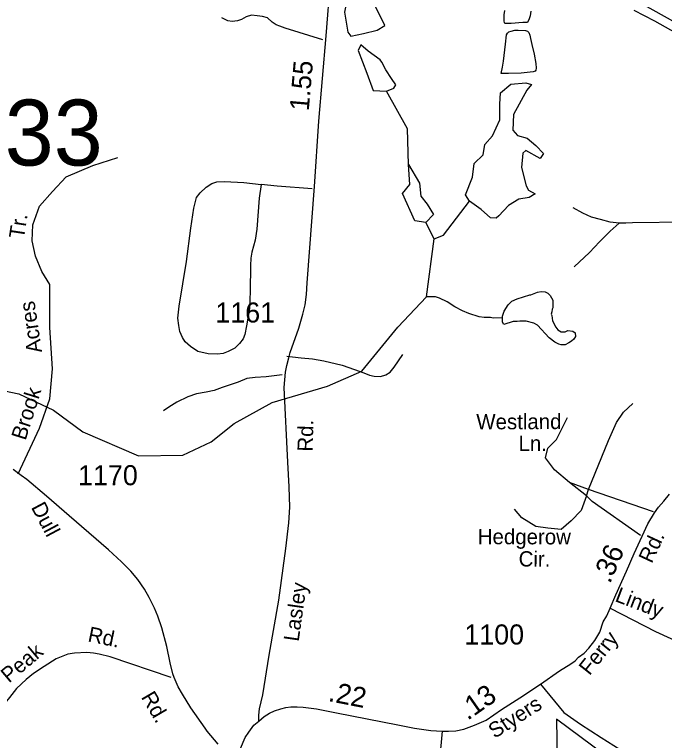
# Model space of a CAD drawing. Extents: x 1547597 to 1699558, y 810033 to 920809.
# Drawn here: x 1580417 to 1584459, y 847300 to 851817 of the extents above; entities that cross this region are included whole.
import ezdxf

# ---------------------------------------------------------------- set-up
doc = ezdxf.new("R2010")
doc.units = 0
for name, color, linetype in [('Exist Boundary Political City Limit New', 7, 'Continuous'), ('Exist Hydrographic Misc Water Feature', 7, 'Continuous'), ('Exist Road Non-System Type 51', 7, 'Continuous'), ('Exist Road Non-System Type 51 Label', 7, 'Continuous'), ('Exist Road Primary US Divided Attributed', 7, 'Continuous'), ('Exist Road Secondary Mileage Hundredths English Label', 7, 'Continuous'), ('Exist Road Secondary Structure Pipe Number Label', 7, 'Continuous'), ('Exist Road Secondary Type 51 Attributed', 7, 'Continuous'), ('Exist Road Secondary Type 51 Label', 7, 'Continuous'), ('Exist Road Secondary Type 51 Number Label', 7, 'Continuous'), ('Map Preparation Boundary City Limit Buffer Line', 7, 'Continuous')]:
    doc.layers.add(name, color=color, linetype=linetype)

msp = doc.modelspace()

# ---------------------------------------------------------------- linework, layer by layer
at = {"layer": 'Exist Boundary Political City Limit New'}
msp.add_lwpolyline([(1584449.8, 846940.3), (1583788.1, 847433.2), (1583808.3, 846129.1)], dxfattribs=at)
at = {"layer": 'Exist Hydrographic Misc Water Feature'}
for points in [[(1582621.5, 851982.6), (1582525, 851980), (1582492.9, 851942.4), (1582468.8, 851832.4), (1582490.2, 851706.4), (1582509, 851682.2), (1582586.7, 851698.3), (1582672.4, 851719.8), (1582720.7, 851749.3), (1582664.4, 851861.9), (1582621.5, 851982.6)], [(1583627.8, 851837.8), (1583623.1, 851809.1), (1583618.6, 851790), (1583606.8, 851768), (1583579.3, 851766.2), (1583506.7, 851761.5), (1583467.7, 851761.6), (1583464.8, 851765.8), (1583461.5, 851777.9), (1583462.7, 851813.8), (1583466.7, 851841.9)], [(1583635.1, 851629.9), (1583648.8, 851570.5), (1583659.3, 851511.6), (1583661.9, 851482.2), (1583659.9, 851470.7), (1583655.8, 851464.5), (1583643.3, 851460.3), (1583568.9, 851452.8), (1583489.2, 851448.9), (1583443.4, 851449.2), (1583452.9, 851489.1), (1583458.5, 851525.9), (1583470.6, 851632.9), (1583477.8, 851690.6), (1583482.4, 851700.8), (1583491.9, 851709.5), (1583506.2, 851714.1), (1583529, 851719), (1583549.4, 851720), (1583594.8, 851717.9), (1583607.7, 851713.2), (1583615, 851704.6), (1583621.9, 851688.9), (1583626.4, 851667.9), (1583630.1, 851649.2), (1583635.1, 851629.9)], [(1582691.2, 851534.7), (1582616.1, 851588.4), (1582570.6, 851628.6), (1582554.5, 851593.7), (1582608.1, 851451.6), (1582648.3, 851344.3), (1582731.4, 851338.9)], [(1582731.4, 851338.9), (1582776.9, 851357.7), (1582787.7, 851379.2), (1582760.9, 851419.4), (1582726, 851473), (1582701.9, 851521.3), (1582691.2, 851534.7)], [(1583246, 850656.3), (1583221.9, 850693.8), (1583264.8, 850803.8), (1583275.5, 850889.6), (1583331.8, 850943.3), (1583342.5, 851007.7), (1583390.7, 851061.3), (1583436.3, 851160.5), (1583436.3, 851259.8), (1583439, 851329.5), (1583503.3, 851383.1), (1583597.1, 851391.2), (1583631.9, 851380.5), (1583602.4, 851345.6), (1583519.4, 851195.4), (1583516.7, 851096.2), (1583546.2, 851064), (1583605.1, 851047.9), (1583658.7, 851002.3), (1583706.9, 850951.3), (1583685.5, 850921.8), (1583597.1, 850970.1), (1583578.3, 850954), (1583570.3, 850865.5), (1583599.8, 850750.2), (1583613.2, 850723.4), (1583656, 850701.9), (1583618.5, 850677.8), (1583554.2, 850667), (1583489.9, 850629.5), (1583428.3, 850565.1), (1583412.2, 850549), (1583377.3, 850551.7), (1583318.4, 850602.7), (1583246, 850656.3)], [(1583026.1, 850420.4), (1582975.7, 850522.8), (1582906.7, 850533.4), (1582829.7, 850703.4), (1582874.9, 850759.2), (1582866.9, 850884), (1582860.5, 851105.4), (1582731.4, 851338.9)], [(1582866.9, 850884), (1582935.9, 850767.1), (1582943.9, 850687.4), (1582983.7, 850637), (1583023.5, 850573.2), (1582975.7, 850522.8)], [(1583026.1, 850420.4), (1583084.5, 850444.3), (1583246, 850656.3)], [(1579738.9, 849483.7), (1580094.5, 849530), (1580443.5, 849457.2), (1580659.6, 849354.4), (1580840.5, 849219.4), (1581188.5, 849071.2), (1581463.5, 849075.5), (1581640.5, 849157.3), (1581783.6, 849272.5), (1582018.6, 849402.3), (1582362.5, 849503.7), (1582577.6, 849597), (1582800.5, 849870.6), (1582979.3, 850060.4), (1583026.1, 850420.4)], [(1583451.4, 849929.6), (1583451.5, 849939), (1583461.9, 849970.9), (1583486.3, 850010.6), (1583510.6, 850032.3), (1583542.8, 850047.8), (1583621, 850072.9), (1583629, 850072.7), (1583669.2, 850088.2), (1583693.3, 850093.9), (1583717.3, 850091.6), (1583733.2, 850083.4), (1583749, 850069.2), (1583764.7, 850039), (1583764, 849991.1), (1583759.9, 849983.1), (1583759.7, 849967.1), (1583755.6, 849953.2), (1583759.5, 849943.2), (1583763.1, 849911.1), (1583784.7, 849870.9), (1583796.4, 849854.7), (1583816.3, 849842.5), (1583842.3, 849842.2), (1583858.4, 849850), (1583890.4, 849847.5), (1583904.2, 849835.3), (1583905.9, 849813.4), (1583895.7, 849797.5), (1583881.5, 849783.7), (1583865.4, 849773.9), (1583841.3, 849762.2), (1583817.4, 849762.5), (1583801.4, 849766.7), (1583777.6, 849779), (1583741.9, 849805.4), (1583668.8, 849884.3), (1583647, 849896.6), (1583599.1, 849909.2), (1583559.1, 849909.7), (1583543.1, 849905.9), (1583519.1, 849906.2), (1583460.1, 849887.3), (1583451, 849903), (1583451.2, 849915), (1583451.4, 849929.6)], [(1583451.4, 849929.6), (1583394, 849927.3), (1583378, 849931.5), (1583338.1, 849932), (1583306.2, 849936.4), (1583242.4, 849957.2), (1583202.6, 849973.7), (1583154.9, 849998.3), (1583107.3, 850028.9), (1583059.6, 850051.5), (1583035.6, 850059.8), (1582979.3, 850060.4)]]:
    msp.add_lwpolyline(points, dxfattribs=at)
at = {"layer": 'Exist Road Non-System Type 51'}
for points in [[(1582334.7, 851660), (1582100.7, 851732.8), (1582066.9, 851743.3), (1582043.1, 851753.6), (1582019.4, 851769.8), (1581989.7, 851796.5), (1581959.6, 851804.9), (1581925.7, 851809.4), (1581889.8, 851811.9), (1581857.7, 851802.3), (1581829.4, 851786.7), (1581803.2, 851777), (1581771.3, 851773.5), (1581743.2, 851777.8), (1581705.5, 851796.4)], [(1580440, 848959.9), (1580571.3, 849243.8), (1580636.8, 849425.3), (1580651.9, 849611.8), (1580636.8, 849868.9), (1580636.8, 850136.2), (1580586.4, 850216.8), (1580546.1, 850312.6), (1580525.9, 850408.4), (1580531, 850509.2), (1580571.3, 850625.2), (1580651.9, 850715.9), (1580737.5, 850806.7), (1580903.8, 850877.3), (1581059.9, 850927.7)], [(1582267.1, 850731.8), (1582050.6, 850748.4), (1581950.7, 850758.7)], [(1584178.3, 850518), (1584122.2, 850525), (1584060.5, 850541.8), (1584004.5, 850556.6), (1583951, 850581.5), (1583891.4, 850614.3)], [(1584178.3, 850518), (1584121.4, 850469), (1584054.4, 850401.9), (1583993.5, 850336.7), (1583898, 850246)], [(1584927.7, 850529.5), (1584260.2, 850521), (1584218.3, 850519.4), (1584178.3, 850518)], [(1582110.2, 849691.5), (1582199.2, 849680.4), (1582269.1, 849673.4), (1582340.9, 849662.3), (1582454.6, 849634.6), (1582532.3, 849607.4), (1582589.9, 849586.7), (1582623.8, 849572.2), (1582653.7, 849565.8), (1582693.7, 849565.2), (1582725.7, 849574.7), (1582754.1, 849592.3), (1582778.5, 849621.9), (1582831.8, 849701.2)], [(1582081.1, 849575), (1581981.2, 849561.4), (1581913.1, 849558.3), (1581861.2, 849551.2), (1581808.7, 849529.8), (1581708.2, 849495.5), (1581658, 849478.1), (1581607.7, 849466.9), (1581549.5, 849455.7), (1581495.3, 849438.3), (1581426.8, 849405.3), (1581376.3, 849374.1), (1581344, 849350.6)], [(1583986.1, 848861.4), (1584111.3, 849166), (1584160.3, 849279), (1584204.5, 849342.9), (1584263.4, 849396.9)], [(1583868.3, 848905.6), (1583775, 848984.2), (1583718.6, 849057.9), (1583733.3, 849119.3), (1583787.3, 849173.4), (1583856, 849308.5)], [(1583973.8, 848822.1), (1583868.3, 848905.6)], [(1583986.1, 848861.4), (1583868.3, 848905.6)], [(1583973.8, 848822.1), (1583941.9, 848731.3), (1583878.1, 848667.4), (1583816.7, 848613.3), (1583733.3, 848620.7), (1583659.6, 848630.5), (1583571.3, 848684.6), (1583527.1, 848738.6)], [(1583973.8, 848822.1), (1583986.1, 848861.4)], [(1584310.2, 848575.3), (1584010.6, 848787.7), (1583973.8, 848822.1)], [(1584390.2, 848722.1), (1583986.1, 848861.4)], [(1584121.6, 848123.8), (1584402.9, 847978.3), (1584571.2, 847902), (1584663.2, 847844.1), (1584773.7, 847759.8), (1584828.9, 847688.8)], [(1581391.3, 847692.3), (1581011.6, 847819.8), (1580942.8, 847837.7), (1580907.1, 847842.8), (1580866.3, 847847.9), (1580789.9, 847842.8), (1580747.6, 847836.6), (1580675.2, 847807.6), (1580600.6, 847760.7), (1580533.9, 847717.6), (1580489.3, 847680.1), (1580428.5, 847622.9), (1580385.6, 847567.5), (1580338.8, 847510.3), (1580306.2, 847472.7), (1580281.8, 847445), (1580146.6, 847359.1), (1580005.2, 847274.9)]]:
    msp.add_lwpolyline(points, dxfattribs=at)
msp.add_lwpolyline([(1581950.7, 850758.7), (1581939.1, 850674.1), (1581923.8, 850481.8), (1581912.9, 850411.9), (1581893.6, 850337.5), (1581887.2, 850300.3), (1581883.4, 850254.2), (1581882.8, 850095.9), (1581877.6, 849988.2), (1581860.3, 849879.8), (1581850.1, 849826), (1581838.6, 849799.1), (1581815.5, 849769.6), (1581787.3, 849741.4), (1581746.3, 849720.9), (1581714.3, 849706.8), (1581678.4, 849702.9), (1581622.1, 849705.5), (1581556.7, 849720.9), (1581511.9, 849751.6), (1581477.3, 849781.1), (1581460.6, 849806.8), (1581444, 849845.2), (1581438.9, 849882.4), (1581432.5, 849927.3), (1581441.4, 850002.9), (1581485.6, 850280.5), (1581513.8, 850486.9), (1581531.1, 850611.9), (1581547.8, 850678.5), (1581572.1, 850706.8), (1581608, 850742.6), (1581644.5, 850765.1), (1581675.2, 850775.3), (1581722.6, 850777.9), (1581843, 850771.5)], close=True, dxfattribs=at)
at = {"layer": 'Exist Road Primary US Divided Attributed'}
msp.add_lwpolyline([(1578489.7, 854501), (1578601.1, 854463.3), (1580008.3, 853986.7), (1580472.4, 853825.1), (1580622.2, 853773.2), (1580843.4, 853691.9), (1581027.4, 853617.5), (1581220.2, 853535), (1581440.8, 853444.2), (1581580.6, 853375.7), (1581724.5, 853303.8), (1581891.4, 853228.3), (1582021.1, 853157.5), (1582160.3, 853082), (1582406.3, 852952.3), (1582786.1, 852742.3), (1584705.4, 851668.3), (1584967.6, 851548.7)], dxfattribs=at)
at = {"layer": 'Exist Road Secondary Type 51 Attributed'}
for points in [[(1581935.6, 847420.9), (1581935.6, 847456.3), (1581940.9, 847497.6), (1581961, 847583.7), (1581999.9, 847830.8), (1582060.9, 848172.3), (1582105.2, 848493.7), (1582122.9, 848654.1), (1582128.5, 848752), (1582125.5, 848877), (1582116.4, 849031.6), (1582094.6, 849496.3), (1582101.9, 849591.8), (1582111.4, 849632.5), (1582122.6, 849680.9), (1582131.1, 849713.3), (1582185.1, 849864.9), (1582209.9, 849952.8), (1582223.7, 850010.6), (1582233.2, 850073.7), (1582237.9, 850148), (1582281.5, 850746.6), (1582309.5, 851152.9), (1582354.7, 851683.1), (1582382.4, 852027)], [(1584268.4, 851843.1), (1584397, 851777.5), (1584563, 851683.1), (1584925.1, 851449), (1584959.3, 851436)], [(1581684.1, 847277.1), (1581615, 847357.9), (1581601.8, 847376), (1581513.2, 847503.1), (1581460.8, 847587), (1581435.3, 847634.5), (1581410.6, 847692), (1581402.2, 847714.5), (1581384.2, 847783.4), (1581363.5, 847884.7), (1581333.1, 848001.2), (1581307.1, 848072.8), (1581287.7, 848123), (1581255.1, 848189.8), (1581225.6, 848242.2), (1581184.2, 848302.3), (1581139.3, 848353.4), (1581082, 848412.2), (1581001.4, 848485.5), (1580755.6, 848698.3), (1580616.4, 848819.4), (1580493.5, 848924.3), (1580457.9, 848949.4), (1580409, 848985)], [(1583688.4, 847649.8), (1583806.9, 847732.3), (1583876.2, 847776.6), (1583903.4, 847796), (1583924.6, 847817.2), (1583960.6, 847843.8), (1583989.5, 847874.5), (1584025.4, 847921), (1584057.9, 847972.9), (1584078.2, 848038.5), (1584100.8, 848076), (1584121.6, 848123.8), (1584156.6, 848205.4), (1584223.9, 848353.3), (1584271.7, 848463.6), (1584320, 848570.4), (1584355.7, 848647), (1584398.2, 848716.6), (1584421.5, 848751.4), (1584455.7, 848788.6), (1584490.9, 848832.8)], [(1583075.6, 847357.3), (1583115.7, 847357.3), (1583161.9, 847359.2), (1583212.2, 847370.6), (1583278.5, 847395.7), (1583351, 847426.6), (1583446, 847493.4), (1583559.1, 847565.7), (1583688.4, 847649.8)], [(1583688.4, 847649.8), (1583832.7, 847474.8), (1583937.3, 847400.9), (1584066.5, 847317.8), (1584183.4, 847243.9)], [(1581935.6, 847420.9), (1581968.7, 847448.7), (1582003.5, 847468.9), (1582034.3, 847484.3), (1582072.6, 847496.7), (1582105.2, 847505), (1582135.6, 847508.6), (1582174.4, 847509.9), (1582211.8, 847507.7), (1582295.1, 847496.4), (1582418.4, 847471.3), (1582800.8, 847396.5), (1582905.2, 847376.6), (1583006.5, 847362.1), (1583075.6, 847357.3)], [(1581793.8, 847180.8), (1581852, 847317.6), (1581874.4, 847351.7), (1581904.8, 847395.4), (1581935.6, 847420.9)], [(1583075.6, 847357.3), (1583059.8, 847177.1)]]:
    msp.add_lwpolyline(points, dxfattribs=at)
at = {"layer": 'Map Preparation Boundary City Limit Buffer Line'}
msp.add_lwpolyline([(1584449.8, 846940.3), (1583788.1, 847433.2), (1583808.3, 846129.1)], dxfattribs=at)

# ---------------------------------------------------------------- texts
at = {"layer": 'Exist Road Non-System Type 51 Label'}
for s, rotation, p in [('Tr.', 81.4471, (1580475.1, 850417.9)), ('Acres', 98.5386, (1580588.1, 849717.5)), ('Brook', 72.4765, (1580484.8, 849162.5)), ('Westland', 0.2175, (1583289.3, 849235.3)), ('Ln.', 359.8107, (1583551.5, 849101.2)), ('Hedgerow', 359.8554, (1583298.2, 848521.1)), ('Cir.', 359.278, (1583551.8, 848383.1)), ('Lindy', 339.1534, (1584146.1, 848167.9)), ('Rd.', 348.327, (1580867.7, 847916.8)), ('Peak', 40.0575, (1580381.6, 847653.8))]:
    msp.add_text(s, height=95, rotation=rotation, dxfattribs=at).set_placement(p)
at = {"layer": 'Exist Road Secondary Mileage Hundredths English Label'}
for s, height, rotation, p in [('1.55', 120, 85.0457, (1582246.7, 851214.2)), ('.36', 125, 66.5799, (1584120, 848270.7)), ('.22', 125, 348.9187, (1582363.2, 847545.8)), ('.13', 125, 35.1124, (1583235, 847421.4))]:
    msp.add_text(s, height=height, rotation=rotation, dxfattribs=at).set_placement(p)
at = {"layer": 'Exist Road Secondary Structure Pipe Number Label'}
msp.add_text('P133', height=410.1, dxfattribs=at).set_placement((1579684.7, 850877.2))
at = {"layer": 'Exist Road Secondary Type 51 Label'}
for s, rotation, p in [('Rd.', 88.6252, (1582271.2, 849096.3)), ('Dull', 298.073, (1580517.3, 848751.2)), ('Rd.', 65.0541, (1584380.1, 848396.6)), ('Lasley', 81.9349, (1582183.8, 847912)), ('Ferry', 51.4199, (1583993, 847699.7)), ('Rd.', 300.3438, (1581201.5, 847570.1)), ('Styers', 32.5901, (1583402.7, 847309.1))]:
    msp.add_text(s, height=95, rotation=rotation, dxfattribs=at).set_placement(p)
at = {"layer": 'Exist Road Secondary Type 51 Number Label'}
for s, p in [('1161', (1581665.6, 849900.4)), ('1170', (1580811.5, 848887.8)), ('1100', (1583214.2, 847897))]:
    msp.add_text(s, height=125, dxfattribs=at).set_placement(p)

doc.saveas('drawing.dxf')
